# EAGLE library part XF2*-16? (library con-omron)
OMRON FPC Connector Source : http://www.omron.com/ecb/products/pdf/fpc.pdf
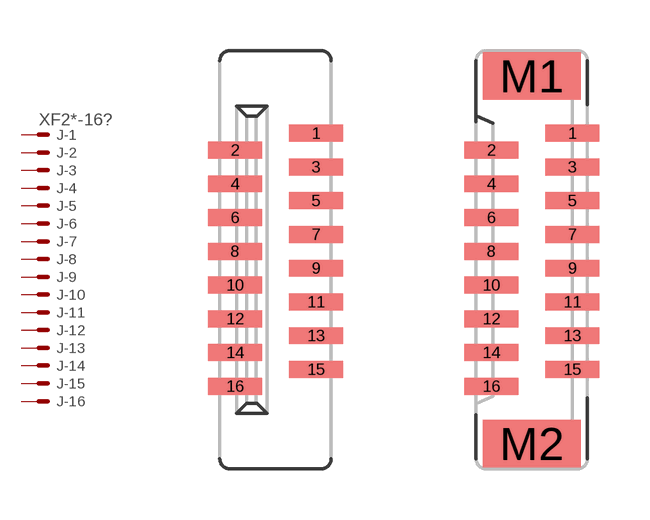
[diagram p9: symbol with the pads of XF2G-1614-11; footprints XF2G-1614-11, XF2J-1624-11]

Designator prefix J; gates -1=PV -2=P -3=P -4=P -5=P -6=P -7=P -8=P -9=P -10=P -11=P -12=P -13=P -14=P -15=P -16=P

## XF2G-1614-11 (MF: OMRON COMPONENTS USA; MPN: XF2G-1614-11; OC_FARNELL: 4785990; OC_NEWARK: 29C7833)  [XF2G-1614-11]
1  -1:MSV  pas
2  -2:MS  pas
3  -3:MS  pas
4  -4:MS  pas
5  -5:MS  pas
6  -6:MS  pas
7  -7:MS  pas
8  -8:MS  pas
9  -9:MS  pas
10  -10:MS  pas
11  -11:MS  pas
12  -12:MS  pas
13  -13:MS  pas
14  -14:MS  pas
15  -15:MS  pas
16  -16:MS  pas

## XF2J-1624-11 (MPN: XF2J-1624-11; OC_FARNELL: unknown; OC_NEWARK: 37M0828)  [XF2J-1624-11]
Pads as for XF2G-1614-11

## XF2J-1624-12 (OC_FARNELL: unknown; OC_NEWARK: unknown)  [XF2J-1624-12]
Pads as for XF2G-1614-11

## Footprint XF2G-1614-11 (pad centres in mm)
Non-ZIF Type (0.5 mm-pitch) Source : http://www.omron.com/ecb/products/pdf/fpc.pdf
smd 1.6 x 0.5: 1 1.2,3.75; 2 -1.2,3.25; 3 1.2,2.75; 4 -1.2,2.25; 5 1.2,1.75; 6 -1.2,1.25; 7 1.2,0.75; 8 -1.2,0.25; 9 1.2,-0.25; 10 -1.2,-0.75; 11 1.2,-1.25; 12 -1.2,-1.75; 13 1.2,-2.25; 14 -1.2,-2.75; 15 1.2,-3.25; 16 -1.2,-3.75

## Footprint XF2J-1624-11 (pad centres in mm)
ZIF Slide-locking Type (0.5 mm-pitch) Standard Source : http://www.omron.com/ecb/products/pdf/fpc.pdf
smd 1.6 x 0.5: 1 1.2,3.75; 2 -1.2,3.25; 3 1.2,2.75; 4 -1.2,2.25; 5 1.2,1.75; 6 -1.2,1.25; 7 1.2,0.75; 8 -1.2,0.25; 9 1.2,-0.25; 10 -1.2,-0.75; 11 1.2,-1.25; 12 -1.2,-1.75; 13 1.2,-2.25; 14 -1.2,-2.75; 15 1.2,-3.25; 16 -1.2,-3.75
smd 2.9 x 1.4: M1 0,5.45; M2 0,-5.45

## Footprint XF2J-1624-12 (pad centres in mm)
ZIF Slide-locking Type (0.5 mm-pitch) Reverse Source : http://www.omron.com/ecb/products/pdf/fpc.pdf
smd 1.6 x 0.5: 1 -1.2,3.75; 2 1.2,3.25; 3 -1.2,2.75; 4 1.2,2.25; 5 -1.2,1.75; 6 1.2,1.25; 7 -1.2,0.75; 8 1.2,0.25; 9 -1.2,-0.25; 10 1.2,-0.75; 11 -1.2,-1.25; 12 1.2,-1.75; 13 -1.2,-2.25; 14 1.2,-2.75; 15 -1.2,-3.25; 16 1.2,-3.75
smd 2.9 x 1.4: M1 0,5.45; M2 0,-5.45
